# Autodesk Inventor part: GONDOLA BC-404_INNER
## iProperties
Shininess: 64.0
Length Units: 11272
Angle Units: 11279
Time Units: 11290
Mass Units: 11286
Length Display Precision: 3
Angle Display Precision: 2
Compacted: True
Part Number: GONDOLA BC-404_INNER
Document SubType Name: Modeling
Created: 2004-08
Designer: John Blackburn
Manufacturer: Standard
Standards Organization: Custom
Material: Lexan, Clear
Density: 0.0
Volumn: 0.0
Area: 0.0
PropertySet Name: Model Information
Control State: 0
Master: False
Checked Out: False
Author: John Blackburn
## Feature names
1. Base1
